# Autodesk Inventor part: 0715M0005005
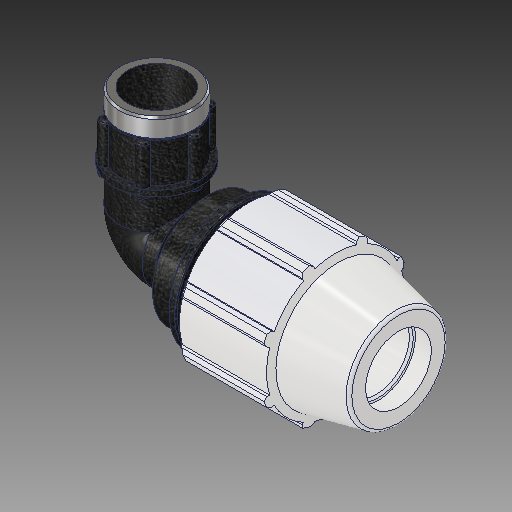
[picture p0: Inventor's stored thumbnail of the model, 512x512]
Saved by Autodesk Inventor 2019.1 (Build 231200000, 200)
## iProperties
Created: 2017-02
Part Number: 0715M0005005
Material: PVC-Piping
Description: PLASSON 90° ELBOW FEMALE ADAPTOR 1/2'' - 1/2''F
Document SubType Name: Modeling
Designer: KIM
Mass: 92.6774 g
Surface Area: 199.44 cm^2
Volume: 66.1981 cm^3
Density: 1.4 g/cm^3
Appearance: PTFE
Author: KIM
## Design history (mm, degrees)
derived "0715M0.ipt"
feature "Solid1::0715M0.ipt"
tag "TaggingFeature1"
body "Solid1"
other parameters: "d_" = 21.2, "E_" = 48.006, "A_" = 77.978, "l_" = 54.102, "l_2" = 19.05, "A_1" = 39.878, "G_" = 18.631, "d105" = 3.63304, "d2" = 21.2, "d4" = 6.49817, "d5" = 19.4945, "d7" = 48.006, "d9" = 11.13971, "d11" = 2.59927, "d13" = 120 deg, "d14" = 31.8, "d15" = 12 deg, "d16" = 41.76522, "d18" = 1.06, "d19" = 35 deg, "d20" = 17.5 deg, "d21" = 44.64558, "d23" = 0, "d25" = 360 deg, "d27" = 0.96012, "d33" = 0.424, "d42" = 28.85186, "d43" = 1.44018, "d46" = 0.636, "d51" = 77.978, "d68" = 2.59927, "d72" = 39.878, "d73" = 24.2203, "d74" = 19.05, "d75" = 27.85335, "d76" = 18.631, "d77" = 20.955, "d79" = 7.4524, "d80" = 0.55893, "d83" = 0, "d84" = 0, "d91" = 36.0045, "d93" = 54.102, "d94" = 18.631, "d95" = 13.0417, "d96" = 7.7978, "d97" = 50 deg, "d98" = 16.7679, "d99" = 0.5, "d100" = 0.5, "d101" = 6.35, "d102" = 24.2203, "d103" = 16.1925, "d104" = 0, "d108" = 360 deg, "d110" = 0.72661
